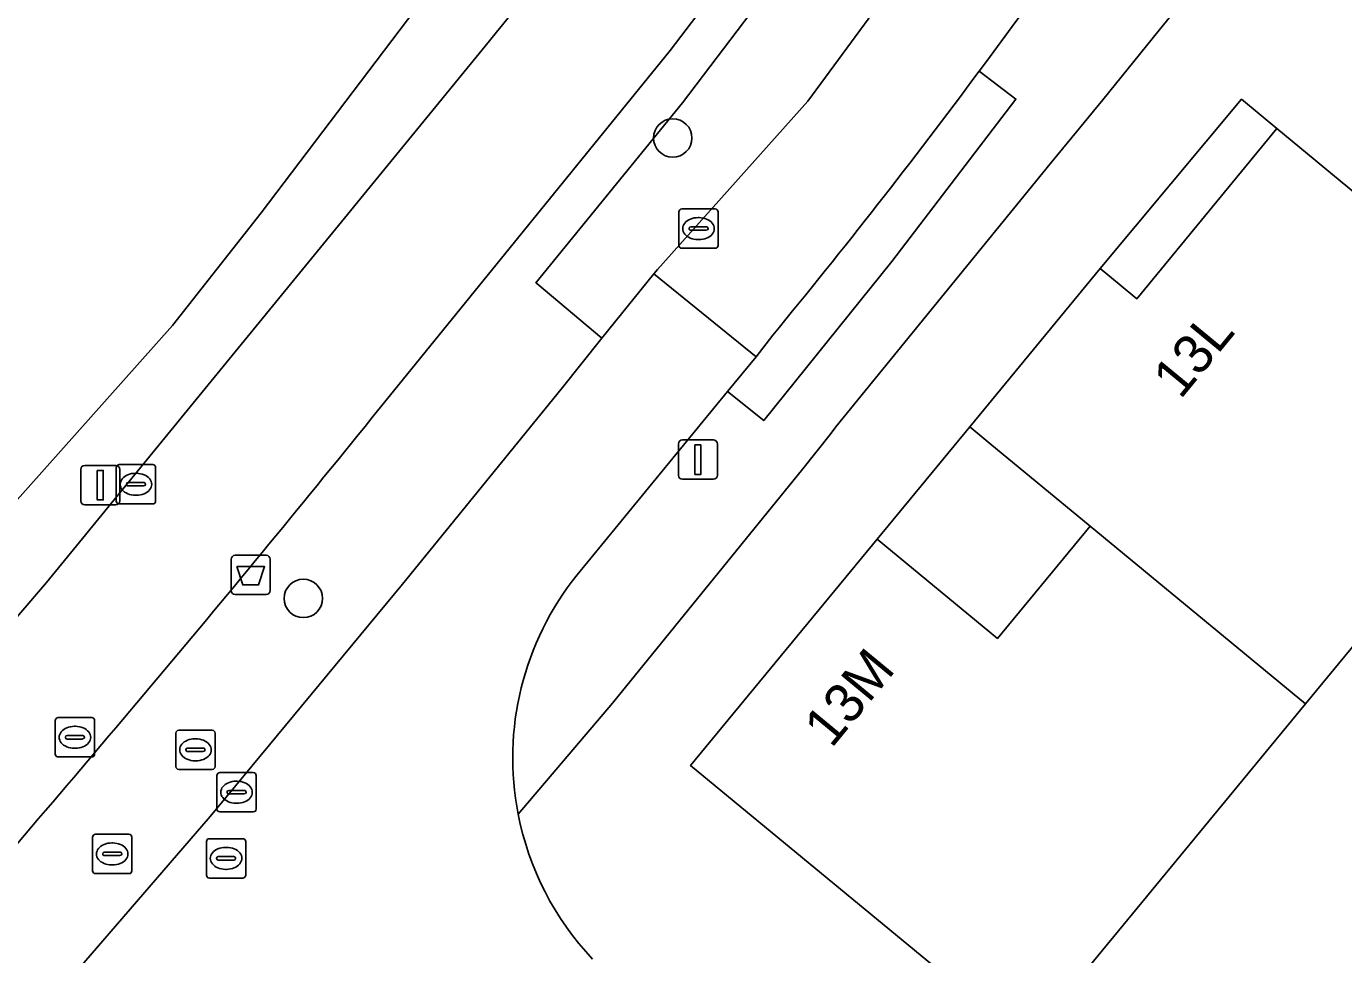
# Model space of a CAD drawing. Extents: x 161772 to 163126, y 383092 to 383917.
# Drawn here: x 161942.28 to 161975.82, y 383294.65 to 383318.27 of the extents above; entities that cross this region are included whole.
import ezdxf

# ---------------------------------------------------------------- set-up
doc = ezdxf.new("R2010")
doc.units = 0
for name, color, linetype in [('IMGEO_Afvalbak', 7, 'Continuous'), ('IMGEO_Berm_open', 7, 'Continuous'), ('IMGEO_Boom', 7, 'Continuous'), ('IMGEO_Erf', 7, 'Continuous'), ('IMGEO_Fietspad_gesloten', 7, 'Continuous'), ('IMGEO_Kolk', 7, 'Continuous'), ('IMGEO_Lichtmast', 7, 'Continuous'), ('IMGEO_Pand', 7, 'Continuous'), ('IMGEO_Pand_nummerreeks', 7, 'Continuous'), ('IMGEO_Parkeervlak_open', 7, 'Continuous'), ('IMGEO_Rijbaan_lokaal_gesloten', 7, 'Continuous'), ('IMGEO_Rijbaan_lokaal_open', 7, 'Continuous'), ('IMGEO_Rioolput', 7, 'Continuous'), ('IMGEO_Voetpad_open', 7, 'Continuous')]:
    doc.layers.add(name, color=color, linetype=linetype)

msp = doc.modelspace()

# ---------------------------------------------------------------- linework, layer by layer
at = {"layer": 'IMGEO_Afvalbak'}
for p, q in [((161947.6, 383304.811), (161948.39, 383304.811)), ((161948.39, 383304.811), (161947.6, 383304.811)), ((161947.5, 383303.911), (161947.5, 383304.711)), ((161947.5, 383304.711), (161947.5, 383303.911)), ((161948.49, 383304.711), (161948.49, 383303.911)), ((161948.49, 383303.911), (161948.49, 383304.711)), ((161948.39, 383303.811), (161947.6, 383303.811)), ((161947.6, 383303.811), (161948.39, 383303.811))]:
    msp.add_line(p, q, dxfattribs=at)
msp.add_lwpolyline([(161947.643, 383304.525), (161948.347, 383304.525), (161948.198, 383304.055), (161947.792, 383304.055), (161947.643, 383304.525)], dxfattribs=at)
for centre, start, end in [((161947.6, 383304.711), 90, 180), ((161947.6, 383304.711), 90, 180), ((161948.39, 383304.711), 0, 90), ((161948.39, 383304.711), 360, 90), ((161947.6, 383303.911), 180, 270), ((161947.6, 383303.911), 180, 270), ((161948.39, 383303.911), 270, 0), ((161948.39, 383303.911), 270, 0)]:
    msp.add_arc(centre, 0.1, start, end, dxfattribs=at)
at = {"layer": 'IMGEO_Berm_open'}
for points in [[(161965.764, 383327.377), (161960.302, 383319.794), (161958.672, 383317.649), (161951.08, 383308.304)], [(161936.941, 383286.844), (161937.725, 383287.694), (161938.545, 383288.593), (161942.733, 383293.261), (161946.965, 383298.168), (161951.858, 383304.076), (161955.895, 383309.039), (161956.93, 383310.332), (161955.277, 383311.727), (161955.257, 383311.744), (161958.985, 383316.324), (161961.426, 383319.531), (161961.064, 383319.803), (161964.615, 383324.66), (161964.958, 383324.39), (161966.144, 383326.081)]]:
    msp.add_lwpolyline(points, dxfattribs=at)
msp.add_arc((161591.388, 383599.05), 462.506, 318.86018, 321.05072, dxfattribs=at)
at = {"layer": 'IMGEO_Boom'}
for centre in [(161958.739, 383315.426), (161949.335, 383303.713)]:
    msp.add_circle(centre, 0.489, dxfattribs=at)
at = {"layer": 'IMGEO_Erf'}
msp.add_lwpolyline([(161924.879, 383329.289), (161917.722, 383317.318), (161908.185, 383302.04), (161906.674, 383300.084), (161904.997, 383297.167), (161901.213, 383291.611), (161900.058, 383290.19), (161899.854, 383289.876), (161906.619, 383283.229), (161908.3, 383284.957), (161901.974, 383290.839), (161905.957, 383295.079), (161907.106, 383293.995), (161908.521, 383295.495), (161916.425, 383288.039), (161912.104, 383283.459), (161916.662, 383279.077), (161922.701, 383285.219), (161925, 383287.557), (161938.061, 383301.283), (161937.818, 383301.48), (161946.008, 383310.656), (161948.264, 383313.526), (161954.519, 383321.774)], dxfattribs=at)
for points in [[(161974.112, 383315.664), (161973.219, 383316.411), (161969.617, 383312.103), (161970.102, 383311.705), (161970.549, 383311.337)], [(161969.361, 383305.552), (161966.808, 383307.655), (161966.298, 383308.075), (161963.945, 383305.221), (161967.005, 383302.695)]]:
    msp.add_lwpolyline(points, close=True, dxfattribs=at)
at = {"layer": 'IMGEO_Fietspad_gesloten'}
for points in [[(161951.08, 383308.304), (161958.672, 383317.649), (161960.302, 383319.794), (161965.764, 383327.377)], [(161953.961, 383317.758), (161942.798, 383304.121), (161935.389, 383295.477), (161886.612, 383242.159)]]:
    msp.add_lwpolyline(points, dxfattribs=at)
for centre, radius, start, end in [((161873.405, 383383.756), 104.139, 320.6731, 324.78693), ((161591.388, 383599.05), 462.506, 318.86018, 321.05072)]:
    msp.add_arc(centre, radius, start, end, dxfattribs=at)
at = {"layer": 'IMGEO_Kolk'}
for p, q in [((161958.894, 383312.695), (161958.894, 383313.547)), ((161958.969, 383313.621), (161959.821, 383313.621)), ((161959.895, 383313.547), (161959.895, 383312.695)), ((161959.382, 383313.401), (161959.407, 383313.401)), ((161959.153, 383313.115), (161959.153, 383313.127)), ((161959.591, 383313.078), (161959.193, 383313.078)), ((161959.196, 383313.164), (161959.594, 383313.164)), ((161959.405, 383312.841), (161959.38, 383312.841)), ((161959.637, 383313.127), (161959.637, 383313.115)), ((161959.821, 383312.621), (161958.969, 383312.621)), ((161944.574, 383306.191), (161944.574, 383307.043)), ((161944.649, 383307.117), (161945.501, 383307.117)), ((161945.062, 383306.897), (161945.087, 383306.897)), ((161945.575, 383307.043), (161945.575, 383306.191)), ((161944.833, 383306.611), (161944.833, 383306.623)), ((161945.271, 383306.574), (161944.873, 383306.574)), ((161944.876, 383306.66), (161945.274, 383306.66)), ((161945.317, 383306.623), (161945.317, 383306.611)), ((161945.085, 383306.337), (161945.06, 383306.337)), ((161945.501, 383306.117), (161944.649, 383306.117)), ((161947.135, 383298.357), (161947.135, 383299.209)), ((161947.21, 383299.283), (161948.062, 383299.283)), ((161948.136, 383299.209), (161948.136, 383298.357)), ((161947.394, 383298.777), (161947.394, 383298.789)), ((161947.437, 383298.826), (161947.835, 383298.826)), ((161947.623, 383299.063), (161947.648, 383299.063)), ((161947.878, 383298.789), (161947.878, 383298.777)), ((161947.832, 383298.74), (161947.434, 383298.74)), ((161947.646, 383298.503), (161947.621, 383298.503)), ((161948.062, 383298.283), (161947.21, 383298.283))]:
    msp.add_line(p, q, dxfattribs=at)
for points in [[(161958.894, 383312.695), (161958.894, 383313.547)], [(161958.969, 383313.621), (161959.821, 383313.621)], [(161959.895, 383313.547), (161959.895, 383312.695)], [(161959.821, 383312.621), (161958.969, 383312.621)], [(161944.574, 383306.191), (161944.574, 383307.043)], [(161944.649, 383307.117), (161945.501, 383307.117)], [(161945.575, 383307.043), (161945.575, 383306.191)], [(161945.501, 383306.117), (161944.649, 383306.117)], [(161947.135, 383298.357), (161947.135, 383299.209)], [(161947.21, 383299.283), (161948.062, 383299.283)], [(161948.136, 383299.209), (161948.136, 383298.357)], [(161948.062, 383298.283), (161947.21, 383298.283)]]:
    msp.add_lwpolyline(points, dxfattribs=at)
for centre, radius, start, end in [((161958.971, 383313.545), 0.0765, 91.552, 178.448), ((161958.971, 383313.545), 0.0765, 91.552, 178.448), ((161959.819, 383313.545), 0.0765, 1.552, 88.448), ((161959.819, 383313.545), 0.0765, 1.552, 88.448), ((161959.193, 383313.124), 0.0403, 85.8775, 175.7526), ((161959.19, 383313.114), 0.0366, 178.938, 274.7102), ((161959.594, 383313.121), 0.043, 264.8664, 352.4533), ((161959.598, 383313.126), 0.0386, 1.7309, 96.639), ((161958.971, 383312.697), 0.0765, 181.552, 268.448), ((161958.971, 383312.697), 0.0765, 181.552, 268.448), ((161959.819, 383312.697), 0.0765, 271.552, 358.448), ((161959.819, 383312.697), 0.0765, 271.552, 358.448), ((161944.651, 383307.041), 0.0765, 91.552, 178.448), ((161944.651, 383307.041), 0.0765, 91.552, 178.448), ((161945.499, 383307.041), 0.0765, 1.552, 88.448), ((161945.499, 383307.041), 0.0765, 1.552, 88.448), ((161944.873, 383306.62), 0.0403, 85.8775, 175.7526), ((161944.87, 383306.61), 0.0366, 178.938, 274.7102), ((161945.274, 383306.617), 0.043, 264.8664, 352.4533), ((161945.278, 383306.622), 0.0386, 1.7309, 96.639), ((161944.651, 383306.193), 0.0765, 181.552, 268.448), ((161944.651, 383306.193), 0.0765, 181.552, 268.448), ((161945.499, 383306.193), 0.0765, 271.552, 358.448), ((161945.499, 383306.193), 0.0765, 271.552, 358.448), ((161947.212, 383299.207), 0.0765, 91.552, 178.448), ((161947.212, 383299.207), 0.0765, 91.552, 178.448), ((161948.06, 383299.207), 0.0765, 1.552, 88.448), ((161948.06, 383299.207), 0.0765, 1.552, 88.448), ((161947.434, 383298.786), 0.0403, 85.8775, 175.7526), ((161947.431, 383298.776), 0.0366, 178.938, 274.7102), ((161947.835, 383298.783), 0.043, 264.8664, 352.4533), ((161947.839, 383298.788), 0.0386, 1.7309, 96.639), ((161947.212, 383298.359), 0.0765, 181.552, 268.448), ((161947.212, 383298.359), 0.0765, 181.552, 268.448), ((161948.06, 383298.359), 0.0765, 271.552, 358.448), ((161948.06, 383298.359), 0.0765, 271.552, 358.448)]:
    msp.add_arc(centre, radius, start, end, dxfattribs=at)
for centre, major_axis, ratio, start_param, end_param in [((161959.381, 383313.121), (-0.387, 0.002), 0.722429, 4.712389, 7.853982), ((161959.406, 383313.121), (-0.39, 0.002), 0.717154, 1.570796, 4.712389), ((161945.061, 383306.617), (-0.387, 0.002), 0.722429, 4.712389, 7.853982), ((161945.086, 383306.617), (-0.39, 0.002), 0.717154, 1.570796, 4.712389), ((161947.622, 383298.783), (-0.387, 0.002), 0.722429, 4.712389, 7.853982), ((161947.647, 383298.783), (-0.39, 0.002), 0.717154, 1.570796, 4.712389)]:
    msp.add_ellipse(centre, major_axis=major_axis, ratio=ratio, start_param=start_param, end_param=end_param, dxfattribs=at)
at = {"layer": 'IMGEO_Lichtmast'}
for p, q in [((161958.884, 383306.844), (161958.884, 383307.644)), ((161958.884, 383307.644), (161958.884, 383306.844)), ((161958.984, 383307.744), (161959.774, 383307.744)), ((161959.774, 383307.744), (161958.984, 383307.744)), ((161959.874, 383307.644), (161959.874, 383306.844)), ((161959.874, 383306.844), (161959.874, 383307.644)), ((161943.671, 383306.195), (161943.671, 383306.995)), ((161943.671, 383306.995), (161943.671, 383306.195)), ((161943.771, 383307.095), (161944.561, 383307.095)), ((161944.561, 383307.095), (161943.771, 383307.095)), ((161944.661, 383306.995), (161944.661, 383306.195)), ((161944.661, 383306.195), (161944.661, 383306.995)), ((161959.774, 383306.744), (161958.984, 383306.744)), ((161958.984, 383306.744), (161959.774, 383306.744)), ((161944.561, 383306.095), (161943.771, 383306.095)), ((161943.771, 383306.095), (161944.561, 383306.095))]:
    msp.add_line(p, q, dxfattribs=at)
for points in [[(161959.304, 383307.619), (161959.454, 383307.619), (161959.454, 383306.869), (161959.304, 383306.869), (161959.304, 383307.619)], [(161944.091, 383306.97), (161944.241, 383306.97), (161944.241, 383306.22), (161944.091, 383306.22), (161944.091, 383306.97)]]:
    msp.add_lwpolyline(points, dxfattribs=at)
for centre, start, end in [((161958.984, 383307.644), 90, 180), ((161958.984, 383307.644), 90, 180), ((161959.774, 383307.644), 0, 90), ((161959.774, 383307.644), 360, 90), ((161943.771, 383306.995), 90, 180), ((161943.771, 383306.995), 90, 180), ((161944.561, 383306.995), 0, 90), ((161944.561, 383306.995), 360, 90), ((161958.984, 383306.844), 180, 270), ((161958.984, 383306.844), 180, 270), ((161959.774, 383306.844), 270, 0), ((161959.774, 383306.844), 270, 0), ((161943.771, 383306.195), 180, 270), ((161943.771, 383306.195), 180, 270), ((161944.561, 383306.195), 270, 0), ((161944.561, 383306.195), 270, 0)]:
    msp.add_arc(centre, 0.1, start, end, dxfattribs=at)
at = {"layer": 'IMGEO_Pand'}
for points in [[(161981.734, 383309.38), (161974.112, 383315.664), (161970.549, 383311.337), (161970.102, 383311.705), (161969.617, 383312.103), (161966.298, 383308.075), (161966.808, 383307.655), (161969.361, 383305.552), (161974.85, 383301.031), (161977.847, 383304.666)], [(161974.85, 383301.031), (161969.361, 383305.552), (161967.005, 383302.695), (161963.945, 383305.221), (161959.192, 383299.463), (161967.744, 383292.413)], [(161987.446, 383295.992), (161987.81, 383296.45), (161977.847, 383304.666), (161974.85, 383301.031), (161967.744, 383292.413), (161977.726, 383284.185), (161982.568, 383290.067)]]:
    msp.add_lwpolyline(points, close=True, dxfattribs=at)
at = {"layer": 'IMGEO_Parkeervlak_open'}
msp.add_lwpolyline([(161966.144, 383326.081), (161964.958, 383324.39), (161961.426, 383319.531), (161958.985, 383316.324), (161955.257, 383311.744), (161955.277, 383311.727), (161956.93, 383310.332), (161958.255, 383311.968), (161958.349, 383312.084), (161962.174, 383316.363), (161967.141, 383323.116), (161968.871, 383325.63)], dxfattribs=at)
at = {"layer": 'IMGEO_Rijbaan_lokaal_gesloten'}
msp.add_lwpolyline([(161956.302, 383304.313), (161960.136, 383308.977), (161960.862, 383309.86), (161958.255, 383311.968), (161956.93, 383310.332), (161955.895, 383309.039), (161951.858, 383304.076), (161946.965, 383298.168), (161942.733, 383293.261), (161938.545, 383288.593), (161941.028, 383286.586), (161943.672, 383289.284)], dxfattribs=at)
for centre, radius, start, end in [((161962.117, 383299.653), 7.452, 141.2903, 191.045), ((161962.124, 383299.656), 7.459, 191.0593, 223.3554)]:
    msp.add_arc(centre, radius, start, end, dxfattribs=at)
at = {"layer": 'IMGEO_Rijbaan_lokaal_open'}
msp.add_lwpolyline([(161968.871, 383325.63), (161967.141, 383323.116), (161962.174, 383316.363), (161958.349, 383312.084), (161958.255, 383311.968), (161960.862, 383309.86), (161961.284, 383310.407)], dxfattribs=at)
for centre, radius, start, end in [((161810.841, 383433.102), 194.147, 323.31816, 326.28176), ((161828.645, 383419.611), 171.809, 320.53481, 323.37939)]:
    msp.add_arc(centre, radius, start, end, dxfattribs=at)
at = {"layer": 'IMGEO_Rioolput'}
for p, q in [((161943.021, 383299.754), (161943.021, 383300.606)), ((161943.096, 383300.68), (161943.948, 383300.68)), ((161943.509, 383300.46), (161943.534, 383300.46)), ((161944.022, 383300.606), (161944.022, 383299.754)), ((161943.28, 383300.174), (161943.28, 383300.186)), ((161943.718, 383300.137), (161943.32, 383300.137)), ((161943.323, 383300.223), (161943.721, 383300.223)), ((161943.764, 383300.186), (161943.764, 383300.174)), ((161946.089, 383299.436), (161946.089, 383300.288)), ((161946.164, 383300.362), (161947.016, 383300.362)), ((161946.577, 383300.142), (161946.602, 383300.142)), ((161947.09, 383300.288), (161947.09, 383299.436)), ((161943.532, 383299.9), (161943.507, 383299.9)), ((161946.348, 383299.856), (161946.348, 383299.868)), ((161946.786, 383299.819), (161946.388, 383299.819)), ((161946.391, 383299.905), (161946.789, 383299.905)), ((161946.832, 383299.868), (161946.832, 383299.856)), ((161943.948, 383299.68), (161943.096, 383299.68)), ((161946.6, 383299.582), (161946.575, 383299.582)), ((161947.016, 383299.362), (161946.164, 383299.362)), ((161943.97, 383296.787), (161943.97, 383297.639)), ((161944.045, 383297.713), (161944.897, 383297.713)), ((161944.458, 383297.493), (161944.483, 383297.493)), ((161944.971, 383297.639), (161944.971, 383296.787)), ((161946.868, 383296.675), (161946.868, 383297.527)), ((161946.943, 383297.601), (161947.795, 383297.601)), ((161947.869, 383297.527), (161947.869, 383296.675)), ((161944.229, 383297.207), (161944.229, 383297.219)), ((161944.667, 383297.17), (161944.269, 383297.17)), ((161944.272, 383297.256), (161944.67, 383297.256)), ((161944.713, 383297.219), (161944.713, 383297.207)), ((161947.127, 383297.095), (161947.127, 383297.107)), ((161947.17, 383297.144), (161947.568, 383297.144)), ((161947.356, 383297.381), (161947.381, 383297.381)), ((161947.611, 383297.107), (161947.611, 383297.095)), ((161944.481, 383296.933), (161944.456, 383296.933)), ((161947.565, 383297.058), (161947.167, 383297.058)), ((161947.379, 383296.821), (161947.354, 383296.821)), ((161944.897, 383296.713), (161944.045, 383296.713)), ((161947.795, 383296.601), (161946.943, 383296.601))]:
    msp.add_line(p, q, dxfattribs=at)
for points in [[(161943.021, 383299.754), (161943.021, 383300.606)], [(161943.096, 383300.68), (161943.948, 383300.68)], [(161944.022, 383300.606), (161944.022, 383299.754)], [(161946.089, 383299.436), (161946.089, 383300.288)], [(161946.164, 383300.362), (161947.016, 383300.362)], [(161947.09, 383300.288), (161947.09, 383299.436)], [(161943.948, 383299.68), (161943.096, 383299.68)], [(161947.016, 383299.362), (161946.164, 383299.362)], [(161943.97, 383296.787), (161943.97, 383297.639)], [(161944.045, 383297.713), (161944.897, 383297.713)], [(161944.971, 383297.639), (161944.971, 383296.787)], [(161946.868, 383296.675), (161946.868, 383297.527)], [(161946.943, 383297.601), (161947.795, 383297.601)], [(161947.869, 383297.527), (161947.869, 383296.675)], [(161944.897, 383296.713), (161944.045, 383296.713)], [(161947.795, 383296.601), (161946.943, 383296.601)]]:
    msp.add_lwpolyline(points, dxfattribs=at)
for centre, radius, start, end in [((161943.098, 383300.604), 0.0765, 91.552, 178.448), ((161943.098, 383300.604), 0.0765, 91.552, 178.448), ((161943.946, 383300.604), 0.0765, 1.552, 88.448), ((161943.946, 383300.604), 0.0765, 1.552, 88.448), ((161943.32, 383300.183), 0.0403, 85.8775, 175.7526), ((161943.317, 383300.173), 0.0366, 178.938, 274.7102), ((161943.721, 383300.18), 0.043, 264.8664, 352.4533), ((161943.725, 383300.185), 0.0386, 1.7309, 96.639), ((161946.166, 383300.286), 0.0765, 91.552, 178.448), ((161946.166, 383300.286), 0.0765, 91.552, 178.448), ((161947.014, 383300.286), 0.0765, 1.552, 88.448), ((161947.014, 383300.286), 0.0765, 1.552, 88.448), ((161946.388, 383299.865), 0.0403, 85.8775, 175.7526), ((161946.385, 383299.855), 0.0366, 178.938, 274.7102), ((161946.789, 383299.862), 0.043, 264.8664, 352.4533), ((161946.793, 383299.867), 0.0386, 1.7309, 96.639), ((161943.098, 383299.756), 0.0765, 181.552, 268.448), ((161943.098, 383299.756), 0.0765, 181.552, 268.448), ((161943.946, 383299.756), 0.0765, 271.552, 358.448), ((161943.946, 383299.756), 0.0765, 271.552, 358.448), ((161946.166, 383299.438), 0.0765, 181.552, 268.448), ((161946.166, 383299.438), 0.0765, 181.552, 268.448), ((161947.014, 383299.438), 0.0765, 271.552, 358.448), ((161947.014, 383299.438), 0.0765, 271.552, 358.448), ((161944.047, 383297.637), 0.0765, 91.552, 178.448), ((161944.047, 383297.637), 0.0765, 91.552, 178.448), ((161944.895, 383297.637), 0.0765, 1.552, 88.448), ((161944.895, 383297.637), 0.0765, 1.552, 88.448), ((161946.945, 383297.525), 0.0765, 91.552, 178.448), ((161946.945, 383297.525), 0.0765, 91.552, 178.448), ((161947.793, 383297.525), 0.0765, 1.552, 88.448), ((161947.793, 383297.525), 0.0765, 1.552, 88.448), ((161944.269, 383297.216), 0.0403, 85.8775, 175.7526), ((161944.266, 383297.206), 0.0366, 178.938, 274.7102), ((161944.67, 383297.213), 0.043, 264.8664, 352.4533), ((161944.674, 383297.218), 0.0386, 1.7309, 96.639), ((161947.167, 383297.104), 0.0403, 85.8775, 175.7526), ((161947.164, 383297.094), 0.0366, 178.938, 274.7102), ((161947.568, 383297.101), 0.043, 264.8664, 352.4533), ((161947.572, 383297.106), 0.0386, 1.7309, 96.639), ((161944.047, 383296.789), 0.0765, 181.552, 268.448), ((161944.047, 383296.789), 0.0765, 181.552, 268.448), ((161944.895, 383296.789), 0.0765, 271.552, 358.448), ((161944.895, 383296.789), 0.0765, 271.552, 358.448), ((161946.945, 383296.677), 0.0765, 181.552, 268.448), ((161946.945, 383296.677), 0.0765, 181.552, 268.448), ((161947.793, 383296.677), 0.0765, 271.552, 358.448), ((161947.793, 383296.677), 0.0765, 271.552, 358.448)]:
    msp.add_arc(centre, radius, start, end, dxfattribs=at)
for centre, major_axis, ratio, start_param, end_param in [((161943.508, 383300.18), (-0.387, 0.002), 0.722429, 4.712389, 7.853982), ((161943.533, 383300.18), (-0.39, 0.002), 0.717154, 1.570796, 4.712389), ((161946.576, 383299.862), (-0.387, 0.002), 0.722429, 4.712389, 7.853982), ((161946.601, 383299.862), (-0.39, 0.002), 0.717154, 1.570796, 4.712389), ((161944.457, 383297.213), (-0.387, 0.002), 0.722429, 4.712389, 7.853982), ((161944.482, 383297.213), (-0.39, 0.002), 0.717154, 1.570796, 4.712389), ((161947.355, 383297.101), (-0.387, 0.002), 0.722429, 4.712389, 7.853982), ((161947.38, 383297.101), (-0.39, 0.002), 0.717154, 1.570796, 4.712389)]:
    msp.add_ellipse(centre, major_axis=major_axis, ratio=ratio, start_param=start_param, end_param=end_param, dxfattribs=at)
at = {"layer": 'IMGEO_Voetpad_open'}
for points in [[(161954.803, 383298.225), (161957.202, 383301.049), (161962.048, 383307.014), (161962.743, 383307.887), (161962.893, 383308.075), (161968.344, 383314.77), (161968.541, 383315.009), (161969.684, 383316.394), (161971.121, 383318.165), (161973.952, 383321.654), (161976.198, 383324.422), (161976.296, 383324.342), (161976.625, 383324.811), (161981.324, 383334.666), (161984.894, 383344.76), (161986.206, 383348.804), (161987.354, 383352.859)], [(161954.519, 383321.774), (161948.264, 383313.526), (161946.008, 383310.656), (161937.818, 383301.48), (161938.061, 383301.283), (161925, 383287.557), (161922.701, 383285.219), (161916.662, 383279.077), (161912.104, 383283.459), (161904.201, 383290.915), (161907.106, 383293.995), (161905.957, 383295.079), (161901.974, 383290.839), (161908.3, 383284.957), (161906.619, 383283.229), (161913.897, 383276.251), (161910.93, 383273.227), (161886.411, 383246.323)], [(161973.952, 383321.654), (161971.121, 383318.165), (161969.684, 383316.394), (161968.541, 383315.009), (161968.344, 383314.77), (161962.893, 383308.075), (161962.743, 383307.887), (161962.048, 383307.014), (161957.202, 383301.049), (161954.803, 383298.225)], [(161886.612, 383242.159), (161935.389, 383295.477), (161942.798, 383304.121), (161953.961, 383317.758)], [(161966.54, 383317.124), (161967.474, 383316.416), (161964.315, 383312.287), (161961.056, 383308.236), (161960.136, 383308.977), (161956.302, 383304.313)], [(161961.284, 383310.407), (161960.862, 383309.86), (161960.136, 383308.977), (161961.056, 383308.236), (161964.315, 383312.287), (161967.474, 383316.416), (161966.54, 383317.124)], [(161977.726, 383284.185), (161967.744, 383292.413), (161959.192, 383299.463), (161963.945, 383305.221), (161966.298, 383308.075), (161969.617, 383312.103), (161973.219, 383316.411), (161974.112, 383315.664), (161981.734, 383309.38)]]:
    msp.add_lwpolyline(points, dxfattribs=at)
for centre, radius, start, end in [((161810.841, 383433.102), 194.147, 323.31816, 326.28176), ((161873.405, 383383.756), 104.139, 320.6731, 324.78693), ((161828.645, 383419.611), 171.809, 320.53481, 323.37939), ((161962.117, 383299.653), 7.452, 141.2903, 191.045), ((161962.124, 383299.656), 7.459, 191.0593, 223.3554)]:
    msp.add_arc(centre, radius, start, end, dxfattribs=at)

# ---------------------------------------------------------------- texts
at = {"layer": 'IMGEO_Pand_nummerreeks'}
for s, rotation, p in [('13L', 50.5291, (161971.662, 383308.756)), ('13M', 50.4604, (161962.78, 383299.882))]:
    msp.add_text(s, height=1, rotation=rotation, dxfattribs=at).set_placement(p)

doc.saveas('drawing.dxf')
